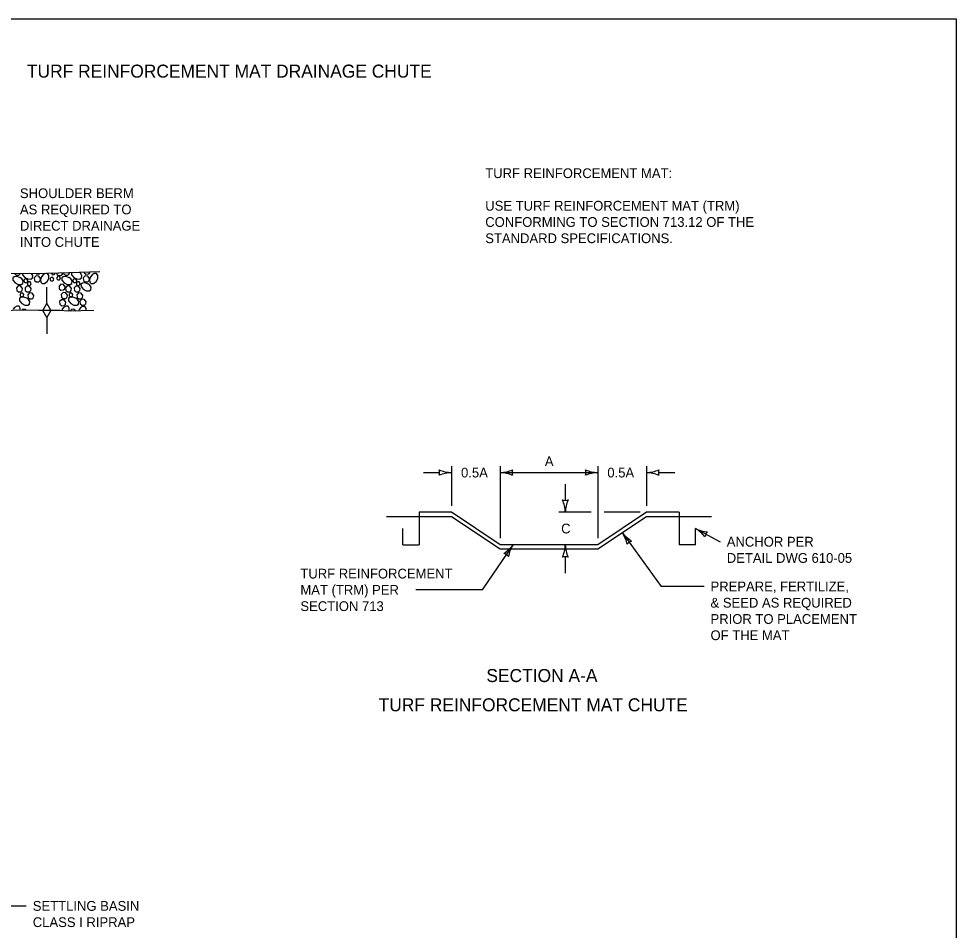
# Model space of a CAD drawing. Extents: x 49991.4 to 50021, y 49987.6 to 50011.4.
# Drawn here: x 50010.98 to 50016.75, y 49993.4 to 49999 of the extents above; entities that cross this region are included whole.
import ezdxf

# ---------------------------------------------------------------- set-up
doc = ezdxf.new("R2010")
doc.units = 0
for name, color, linetype in [('Level 1', 7, 'Continuous'), ('Level 2', 7, 'Continuous'), ('Level 3', 7, 'Continuous')]:
    doc.layers.add(name, color=color, linetype=linetype)

msp = doc.modelspace()

# ---------------------------------------------------------------- linework, layer by layer
at = {"layer": 'Level 1'}
for p, q in [((50011.1546, 49997.2491), (50011.1546, 49997.3491)), ((50011.1296, 49997.2058), (50011.1546, 49997.2491)), ((50011.1546, 49997.2491), (50011.1796, 49997.2058)), ((50011.1546, 49997.1625), (50011.1296, 49997.2058)), ((50011.1789, 49997.2047), (50011.1546, 49997.1625)), ((50011.2508, 49997.2148), (50011.2468, 49997.2047)), ((50011.3549, 49997.2123), (50011.3512, 49997.2029)), ((50011.1546, 49997.1625), (50011.1546, 49997.0625)), ((50013.4449, 49995.9648), (50013.4449, 49995.7648)), ((50015.0449, 49995.9648), (50015.0449, 49995.7648)), ((50013.2449, 49995.9398), (50013.6449, 49995.9398)), ((50013.6449, 49995.9398), (50013.9449, 49995.7398)), ((50014.5449, 49995.7398), (50014.8449, 49995.9398)), ((50014.8449, 49995.9398), (50015.2449, 49995.9398)), ((50013.3449, 49995.7648), (50013.3449, 49995.8648)), ((50015.1449, 49995.7648), (50015.1449, 49995.8648)), ((50013.3449, 49995.7648), (50013.4449, 49995.7648)), ((50013.9449, 49995.7398), (50014.5449, 49995.7398)), ((50015.1449, 49995.7648), (50015.0449, 49995.7648))]:
    msp.add_line(p, q, dxfattribs=at)
msp.add_lwpolyline([(49999.3835, 49998.9992), (50016.7501, 49998.9992), (50016.7501, 49987.7988), (49999.3835, 49987.7988)], close=True, dxfattribs=at)
for points in [[(50011.482, 49997.443), (50011.1627, 49997.4327), (50010.8516, 49997.431), (50010.609, 49997.4042), (50010.4204, 49997.3093), (50010.3553, 49997.2058)], [(50010.9917, 49997.4073), (50010.9725, 49997.4149), (50010.9549, 49997.4134), (50010.9465, 49997.4054), (50010.9468, 49997.3912), (50010.9595, 49997.3749), (50010.9791, 49997.3651), (50010.9976, 49997.3648), (50011.008, 49997.3722), (50011.009, 49997.3869), (50011.0006, 49997.4001), (50010.9909, 49997.4078)], [(50010.9575, 49997.4316), (50010.9576, 49997.4301), (50010.9677, 49997.4217), (50010.9839, 49997.4229), (50010.9915, 49997.4302), (50010.9918, 49997.4318)], [(50011.0061, 49997.4318), (50011.0062, 49997.4254), (50011.0189, 49997.4092), (50011.0386, 49997.3993), (50011.0571, 49997.399), (50011.0675, 49997.4064), (50011.0685, 49997.4212), (50011.0614, 49997.4321)], [(50011.1159, 49997.4022), (50011.1057, 49997.4167), (50011.0893, 49997.4177), (50011.078, 49997.4059), (50011.0796, 49997.3894), (50011.0897, 49997.381), (50011.1059, 49997.3821), (50011.1135, 49997.3895), (50011.1159, 49997.4022)], [(50011.0902, 49997.4323), (50011.0943, 49997.4289), (50011.1104, 49997.4301), (50011.1128, 49997.4324)], [(50011.1247, 49997.4157), (50011.1171, 49997.3965), (50011.1186, 49997.3789), (50011.1265, 49997.3705), (50011.1408, 49997.3708), (50011.1571, 49997.3835), (50011.1669, 49997.4031), (50011.1672, 49997.4216), (50011.1598, 49997.432), (50011.1507, 49997.4326)], [(50011.1444, 49997.4326), (50011.1319, 49997.4246), (50011.1242, 49997.4149)], [(50011.1981, 49997.3998), (50011.192, 49997.4086), (50011.1821, 49997.4091), (50011.1753, 49997.402), (50011.1763, 49997.3921), (50011.1824, 49997.3871), (50011.1921, 49997.3878), (50011.1966, 49997.3922), (50011.1981, 49997.3998)], [(50011.1846, 49997.4334), (50011.185, 49997.4301), (50011.191, 49997.425), (50011.2007, 49997.4258), (50011.2053, 49997.4302), (50011.206, 49997.4341)], [(50011.2385, 49997.407), (50011.2323, 49997.4158), (50011.2225, 49997.4163), (50011.2157, 49997.4093), (50011.2167, 49997.3993), (50011.2227, 49997.3943), (50011.2324, 49997.395), (50011.237, 49997.3994), (50011.2385, 49997.407)], [(50011.2165, 49997.4344), (50011.217, 49997.4295), (50011.2272, 49997.4211), (50011.2433, 49997.4222), (50011.2509, 49997.4296), (50011.2521, 49997.4356)], [(50011.2932, 49997.4073), (50011.274, 49997.4149), (50011.2564, 49997.4134), (50011.2481, 49997.4054), (50011.2483, 49997.3912), (50011.261, 49997.3749), (50011.2807, 49997.3651), (50011.2992, 49997.3648), (50011.3096, 49997.3722), (50011.3106, 49997.3869), (50011.3021, 49997.4001), (50011.2924, 49997.4078)], [(50011.2586, 49997.4358), (50011.2592, 49997.4301), (50011.2693, 49997.4217), (50011.2854, 49997.4229), (50011.293, 49997.4302), (50011.2944, 49997.437)], [(50011.3076, 49997.4374), (50011.3078, 49997.4254), (50011.3205, 49997.4092), (50011.3401, 49997.3993), (50011.3586, 49997.399), (50011.369, 49997.4064), (50011.37, 49997.4212), (50011.3616, 49997.4343), (50011.3558, 49997.4389)], [(50011.4175, 49997.4022), (50011.4073, 49997.4167), (50011.3909, 49997.4177), (50011.3795, 49997.4059), (50011.3812, 49997.3894), (50011.3913, 49997.381), (50011.4074, 49997.3821), (50011.415, 49997.3895), (50011.4175, 49997.4022)], [(50011.3855, 49997.4399), (50011.3857, 49997.4373), (50011.3958, 49997.4289), (50011.412, 49997.4301), (50011.4196, 49997.4374), (50011.4203, 49997.441)], [(50011.4262, 49997.4157), (50011.4186, 49997.3965), (50011.4201, 49997.3789), (50011.4281, 49997.3705), (50011.4424, 49997.3708), (50011.4586, 49997.3835), (50011.4684, 49997.4031), (50011.4687, 49997.4216), (50011.4613, 49997.432), (50011.4466, 49997.433), (50011.4334, 49997.4246), (50011.4257, 49997.4149)], [(50011.0063, 49997.341), (50010.996, 49997.3556), (50010.9797, 49997.3565), (50010.9683, 49997.3447), (50010.97, 49997.3282), (50010.9801, 49997.3198), (50010.9962, 49997.321), (50011.0038, 49997.3283), (50011.0063, 49997.341)], [(50011.0373, 49997.3902), (50011.0312, 49997.399), (50011.0214, 49997.3995), (50011.0145, 49997.3924), (50011.0155, 49997.3825), (50011.0216, 49997.3775), (50011.0313, 49997.3782), (50011.0358, 49997.3826), (50011.0373, 49997.3902)], [(50011.0591, 49997.3404), (50011.0489, 49997.355), (50011.0325, 49997.3559), (50011.0212, 49997.3441), (50011.0228, 49997.3276), (50011.0329, 49997.3192), (50011.0491, 49997.3204), (50011.0567, 49997.3277), (50011.0591, 49997.3404)], [(50011.0585, 49997.3724), (50011.0523, 49997.3812), (50011.0425, 49997.3817), (50011.0357, 49997.3747), (50011.0367, 49997.3648), (50011.0427, 49997.3597), (50011.0524, 49997.3604), (50011.057, 49997.3648), (50011.0585, 49997.3724)], [(50011.2681, 49997.3517), (50011.2579, 49997.3663), (50011.2415, 49997.3672), (50011.2301, 49997.3554), (50011.2318, 49997.3389), (50011.2419, 49997.3305), (50011.258, 49997.3317), (50011.2656, 49997.339), (50011.2681, 49997.3517)], [(50011.3078, 49997.341), (50011.2976, 49997.3556), (50011.2812, 49997.3565), (50011.2699, 49997.3447), (50011.2715, 49997.3282), (50011.2816, 49997.3198), (50011.2978, 49997.321), (50011.3054, 49997.3283), (50011.3078, 49997.341)], [(50011.3389, 49997.3902), (50011.3327, 49997.399), (50011.3229, 49997.3995), (50011.3161, 49997.3924), (50011.3171, 49997.3825), (50011.3231, 49997.3775), (50011.3328, 49997.3782), (50011.3374, 49997.3826), (50011.3389, 49997.3902)], [(50011.3607, 49997.3404), (50011.3505, 49997.355), (50011.3341, 49997.3559), (50011.3227, 49997.3441), (50011.3244, 49997.3276), (50011.3345, 49997.3192), (50011.3506, 49997.3204), (50011.3582, 49997.3277), (50011.3607, 49997.3404)], [(50011.36, 49997.3724), (50011.3539, 49997.3812), (50011.3441, 49997.3817), (50011.3372, 49997.3747), (50011.3382, 49997.3648), (50011.3443, 49997.3597), (50011.354, 49997.3604), (50011.3585, 49997.3648), (50011.36, 49997.3724)], [(50011.4103, 49997.3683), (50011.3912, 49997.3759), (50011.3736, 49997.3744), (50011.3652, 49997.3664), (50011.3655, 49997.3521), (50011.3782, 49997.3359), (50011.3978, 49997.3261), (50011.4163, 49997.3257), (50011.4267, 49997.3331), (50011.4277, 49997.3479), (50011.4192, 49997.361), (50011.4096, 49997.3688)], [(50011.0138, 49997.3037), (50011.0076, 49997.3125), (50010.9978, 49997.313), (50010.991, 49997.3059), (50010.992, 49997.296), (50010.998, 49997.291), (50011.0077, 49997.2917), (50011.0123, 49997.2961), (50011.0138, 49997.3037)], [(50011.0759, 49997.2977), (50011.0657, 49997.3123), (50011.0493, 49997.3132), (50011.038, 49997.3014), (50011.0396, 49997.2849), (50011.0497, 49997.2765), (50011.0659, 49997.2777), (50011.0735, 49997.2851), (50011.0759, 49997.2977)], [(50011.2818, 49997.2999), (50011.2715, 49997.3145), (50011.2552, 49997.3155), (50011.2438, 49997.3037), (50011.2454, 49997.2871), (50011.2555, 49997.2787), (50011.2717, 49997.2799), (50011.2793, 49997.2873), (50011.2818, 49997.2999)], [(50011.3153, 49997.3037), (50011.3092, 49997.3125), (50011.2994, 49997.313), (50011.2925, 49997.3059), (50011.2935, 49997.296), (50011.2996, 49997.291), (50011.3093, 49997.2917), (50011.3139, 49997.2961), (50011.3153, 49997.3037)], [(50011.3775, 49997.2977), (50011.3673, 49997.3123), (50011.3509, 49997.3132), (50011.3395, 49997.3014), (50011.3412, 49997.2849), (50011.3513, 49997.2765), (50011.3674, 49997.2777), (50011.375, 49997.2851), (50011.3775, 49997.2977)], [(50011.0325, 49997.2804), (50011.0134, 49997.288), (50010.9957, 49997.2864), (50010.9874, 49997.2785), (50010.9876, 49997.2642), (50011.0004, 49997.248), (50011.02, 49997.2382), (50011.0385, 49997.2378), (50011.0489, 49997.2452), (50011.0499, 49997.26), (50011.0414, 49997.2731), (50011.0317, 49997.2809)], [(50011.2721, 49997.2563), (50011.2619, 49997.2709), (50011.2455, 49997.2718), (50011.2341, 49997.26), (50011.2358, 49997.2435), (50011.2459, 49997.2351), (50011.262, 49997.2363), (50011.2696, 49997.2436), (50011.2721, 49997.2563)], [(50011.3341, 49997.2804), (50011.3149, 49997.288), (50011.2973, 49997.2864), (50011.2889, 49997.2785), (50011.2892, 49997.2642), (50011.3019, 49997.248), (50011.3215, 49997.2382), (50011.34, 49997.2378), (50011.3504, 49997.2452), (50011.3514, 49997.26), (50011.343, 49997.2731), (50011.3333, 49997.2809)], [(50011.3968, 49997.2592), (50011.3865, 49997.2737), (50011.3702, 49997.2747), (50011.3588, 49997.2629), (50011.3604, 49997.2464), (50011.3706, 49997.238), (50011.3867, 49997.2391), (50011.3943, 49997.2465), (50011.3968, 49997.2592)], [(50011.4448, 49997.2058), (50011.2866, 49997.2008), (50011.2358, 49997.2058), (50011.1066, 49997.2058), (50011.0231, 49997.2079), (50010.9416, 49997.2058), (50010.7182, 49997.2), (50010.3553, 49997.2058)], [(50010.9915, 49997.2071), (50010.9918, 49997.2207), (50010.9844, 49997.2312), (50010.9697, 49997.2321), (50010.9565, 49997.2237), (50010.9488, 49997.214)], [(50011.0279, 49997.2078), (50011.0247, 49997.2124), (50011.0084, 49997.2133), (50011.0027, 49997.2074)], [(50011.2924, 49997.201), (50011.293, 49997.2022), (50011.2933, 49997.2207), (50011.2859, 49997.2312), (50011.2712, 49997.2321), (50011.258, 49997.2237), (50011.2503, 49997.214)], [(50011.3334, 49997.2023), (50011.3263, 49997.2124), (50011.3099, 49997.2133), (50011.2985, 49997.2015), (50011.2986, 49997.2012)], [(50011.3972, 49997.2043), (50011.3975, 49997.2183), (50011.3901, 49997.2287), (50011.3753, 49997.2297), (50011.3622, 49997.2212), (50011.3544, 49997.2115)], [(50015.0449, 49995.9648), (50014.8449, 49995.9648), (50014.5449, 49995.7648), (50013.9449, 49995.7648), (50013.6449, 49995.9648), (50013.4449, 49995.9648)]]:
    msp.add_lwpolyline(points, dxfattribs=at)
at = {"layer": 'Level 3'}
for p, q in [((50013.4715, 49996.2088), (50013.5715, 49996.2088)), ((50013.6449, 49996.2488), (50013.6449, 49996.0048)), ((50013.9449, 49996.2488), (50013.9449, 49995.8048)), ((50013.9449, 49996.2088), (50014.5449, 49996.2088)), ((50014.5449, 49996.2488), (50014.5449, 49995.8048)), ((50014.8449, 49996.2488), (50014.8449, 49996.0048)), ((50014.9184, 49996.2088), (50015.0184, 49996.2088)), ((50014.3449, 49996.1383), (50014.3449, 49996.0383)), ((50014.5049, 49995.9648), (50014.3049, 49995.9648)), ((50014.8049, 49995.9648), (50014.5849, 49995.9648)), ((50015.1449, 49995.8648), (50015.2983, 49995.7839)), ((50014.6949, 49995.8398), (50014.9339, 49995.5087)), ((50013.8348, 49995.4877), (50014.0235, 49995.7648)), ((50014.3449, 49995.6914), (50014.3449, 49995.5914)), ((50015.1983, 49995.5087), (50014.9339, 49995.5087)), ((50013.8348, 49995.4877), (50013.4261, 49995.4877)), ((50010.8554, 49993.5446), (50011.0288, 49993.5446))]:
    msp.add_line(p, q, dxfattribs=at)
for centre, radius, start, end in [((50013.6541, 49996.4309), 0.2223, 247.45601, 267.63952), ((50013.5167, 49996.2088), 0.0548, 342.13882, 17.86118), ((50013.6564, 49995.9761), 0.233, 92.82731, 112.07716), ((50013.9334, 49996.4415), 0.233, 272.82731, 292.07716), ((50013.9358, 49995.9866), 0.2223, 67.45601, 87.63952), ((50014.0731, 49996.2088), 0.0548, 162.13882, 197.86118), ((50014.5541, 49996.4309), 0.2223, 247.45601, 267.63952), ((50014.4167, 49996.2088), 0.0548, 342.13882, 17.86118), ((50014.5564, 49995.9761), 0.233, 92.82731, 112.07716), ((50014.8334, 49996.4415), 0.233, 272.82731, 292.07716), ((50014.8358, 49995.9866), 0.2223, 67.45601, 87.63952), ((50014.9731, 49996.2088), 0.0548, 162.13882, 197.86118), ((50014.3449, 49996.093), 0.0548, 252.13882, 287.86118), ((50014.1122, 49995.9533), 0.233, 2.82731, 22.07716), ((50014.5671, 49995.9557), 0.2223, 157.45601, 177.63952), ((50015.0331, 49995.6727), 0.2223, 39.62532, 59.80883), ((50015.2434, 49996.076), 0.233, 244.99662, 264.24647), ((50014.5094, 49995.7173), 0.2223, 13.27019, 33.4537), ((50014.8769, 49995.9853), 0.233, 218.64149, 237.89134), ((50015.2583, 49995.805), 0.0548, 134.30813, 170.03049), ((50013.845, 49995.8974), 0.2223, 303.20996, 323.39347), ((50014.2223, 49995.6434), 0.233, 148.58126, 167.83111), ((50014.1228, 49995.774), 0.2223, 337.45601, 357.63952), ((50014.5776, 49995.7763), 0.233, 182.82731, 202.07716), ((50014.77, 49995.7359), 0.0548, 107.953, 143.67536), ((50013.9513, 49995.6588), 0.0548, 37.89277, 73.61513), ((50014.3449, 49995.6366), 0.0548, 72.13882, 107.86118)]:
    msp.add_arc(centre, radius, start, end, dxfattribs=at)

# ---------------------------------------------------------------- texts
at = {"layer": 'Level 2'}
for s, height, p in [('TURF REINFORCEMENT MAT DRAINAGE CHUTE', 0.08, (50011.0326, 49998.6372)), ('TURF REINFORCEMENT MAT:', 0.06, (50013.8524, 49998.0196)), ('SHOULDER BERM', 0.06, (50010.9897, 49997.8966)), ('USE TURF REINFORCEMENT MAT (TRM)', 0.06, (50013.8524, 49997.8196)), ('AS REQUIRED TO', 0.06, (50010.9897, 49997.7966)), ('DIRECT DRAINAGE', 0.06, (50010.9897, 49997.6966)), ('CONFORMING TO SECTION 713.12 OF THE', 0.06, (50013.8524, 49997.7196)), ('INTO CHUTE', 0.06, (50010.9897, 49997.5966)), ('STANDARD SPECIFICATIONS.', 0.06, (50013.8524, 49997.6196)), ('A', 0.06, (50014.2192, 49996.2488)), ('0.5A', 0.06, (50013.7035, 49996.1788)), ('0.5A', 0.06, (50014.6035, 49996.1788)), ('C', 0.06, (50014.3194, 49995.8348)), ('ANCHOR PER', 0.06, (50015.3383, 49995.7539)), ('DETAIL DWG 610-05', 0.06, (50015.3383, 49995.6539)), ('TURF REINFORCEMENT', 0.06, (50012.7151, 49995.5577)), ('MAT (TRM) PER', 0.06, (50012.7151, 49995.4577)), ('PREPARE, FERTILIZE,', 0.06, (50015.2383, 49995.4787)), ('SECTION 713', 0.06, (50012.7151, 49995.3577)), ('& SEED AS REQUIRED', 0.06, (50015.2383, 49995.3787)), ('PRIOR TO PLACEMENT', 0.06, (50015.2383, 49995.2787)), ('OF THE MAT', 0.06, (50015.2383, 49995.1787)), ('SECTION A-A', 0.08, (50013.8593, 49994.921)), ('TURF REINFORCEMENT MAT CHUTE', 0.08, (50013.1965, 49994.741)), ('SETTLING BASIN ', 0.06, (50011.0688, 49993.5146)), ('CLASS I RIPRAP', 0.06, (50011.0688, 49993.4146))]:
    msp.add_text(s, height=height, dxfattribs=at).set_placement(p)

doc.saveas('drawing.dxf')
